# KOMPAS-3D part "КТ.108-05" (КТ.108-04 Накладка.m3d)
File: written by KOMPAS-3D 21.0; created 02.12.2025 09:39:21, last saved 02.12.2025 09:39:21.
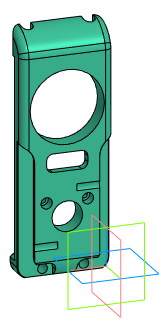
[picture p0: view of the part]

Document properties: Автор: User; Организация: User; Полное имя файла: C:\Users\User\Desktop\Pelorus PRO доработки\накладка\КТ.108-05.m3d

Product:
- Part/product: КТ.108-05
    Комментарий: User

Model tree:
1. Операция без истории:1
